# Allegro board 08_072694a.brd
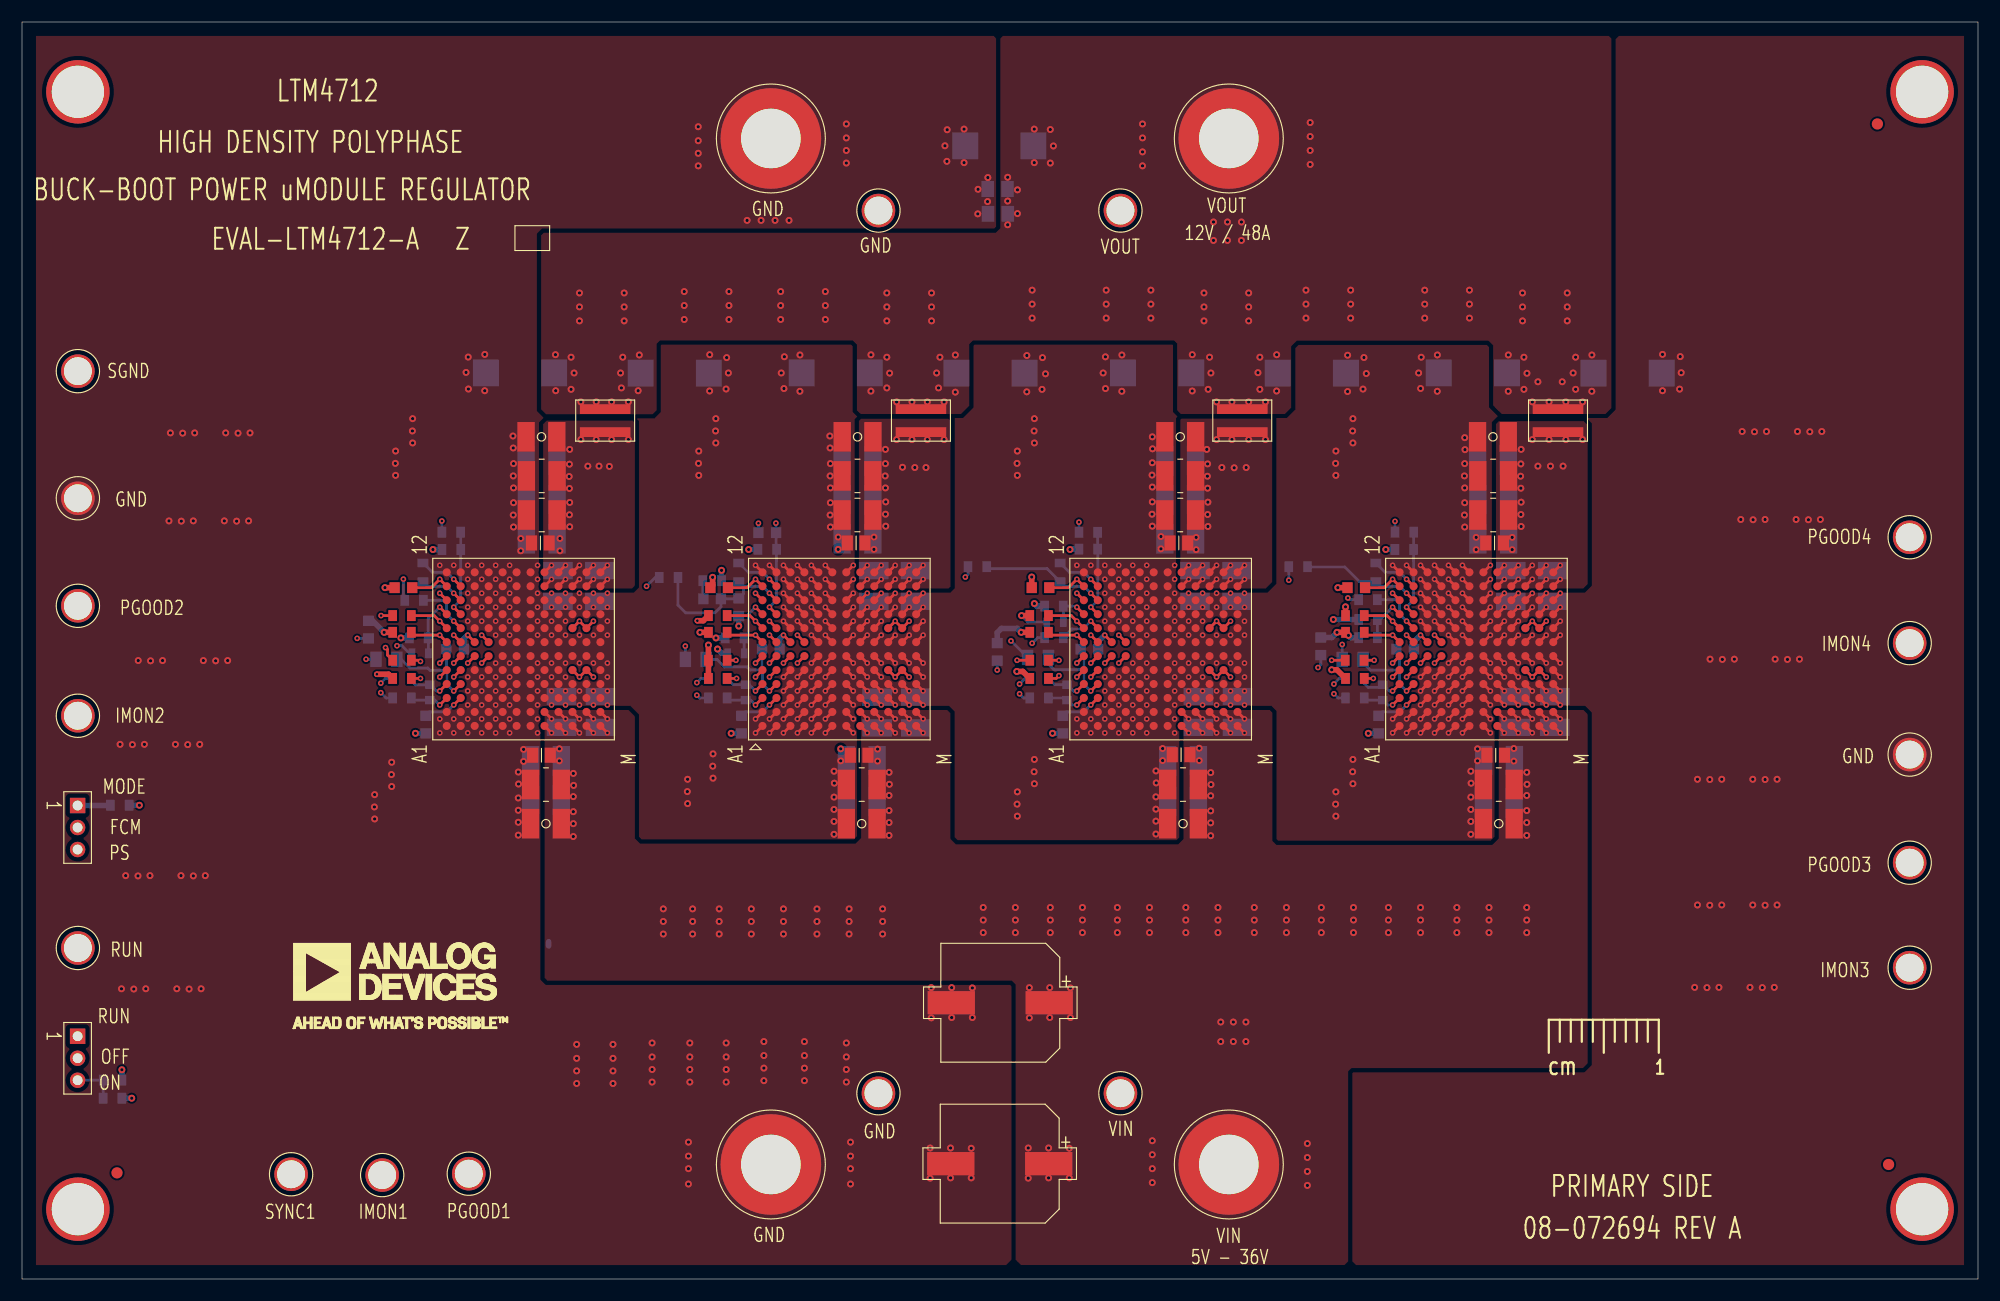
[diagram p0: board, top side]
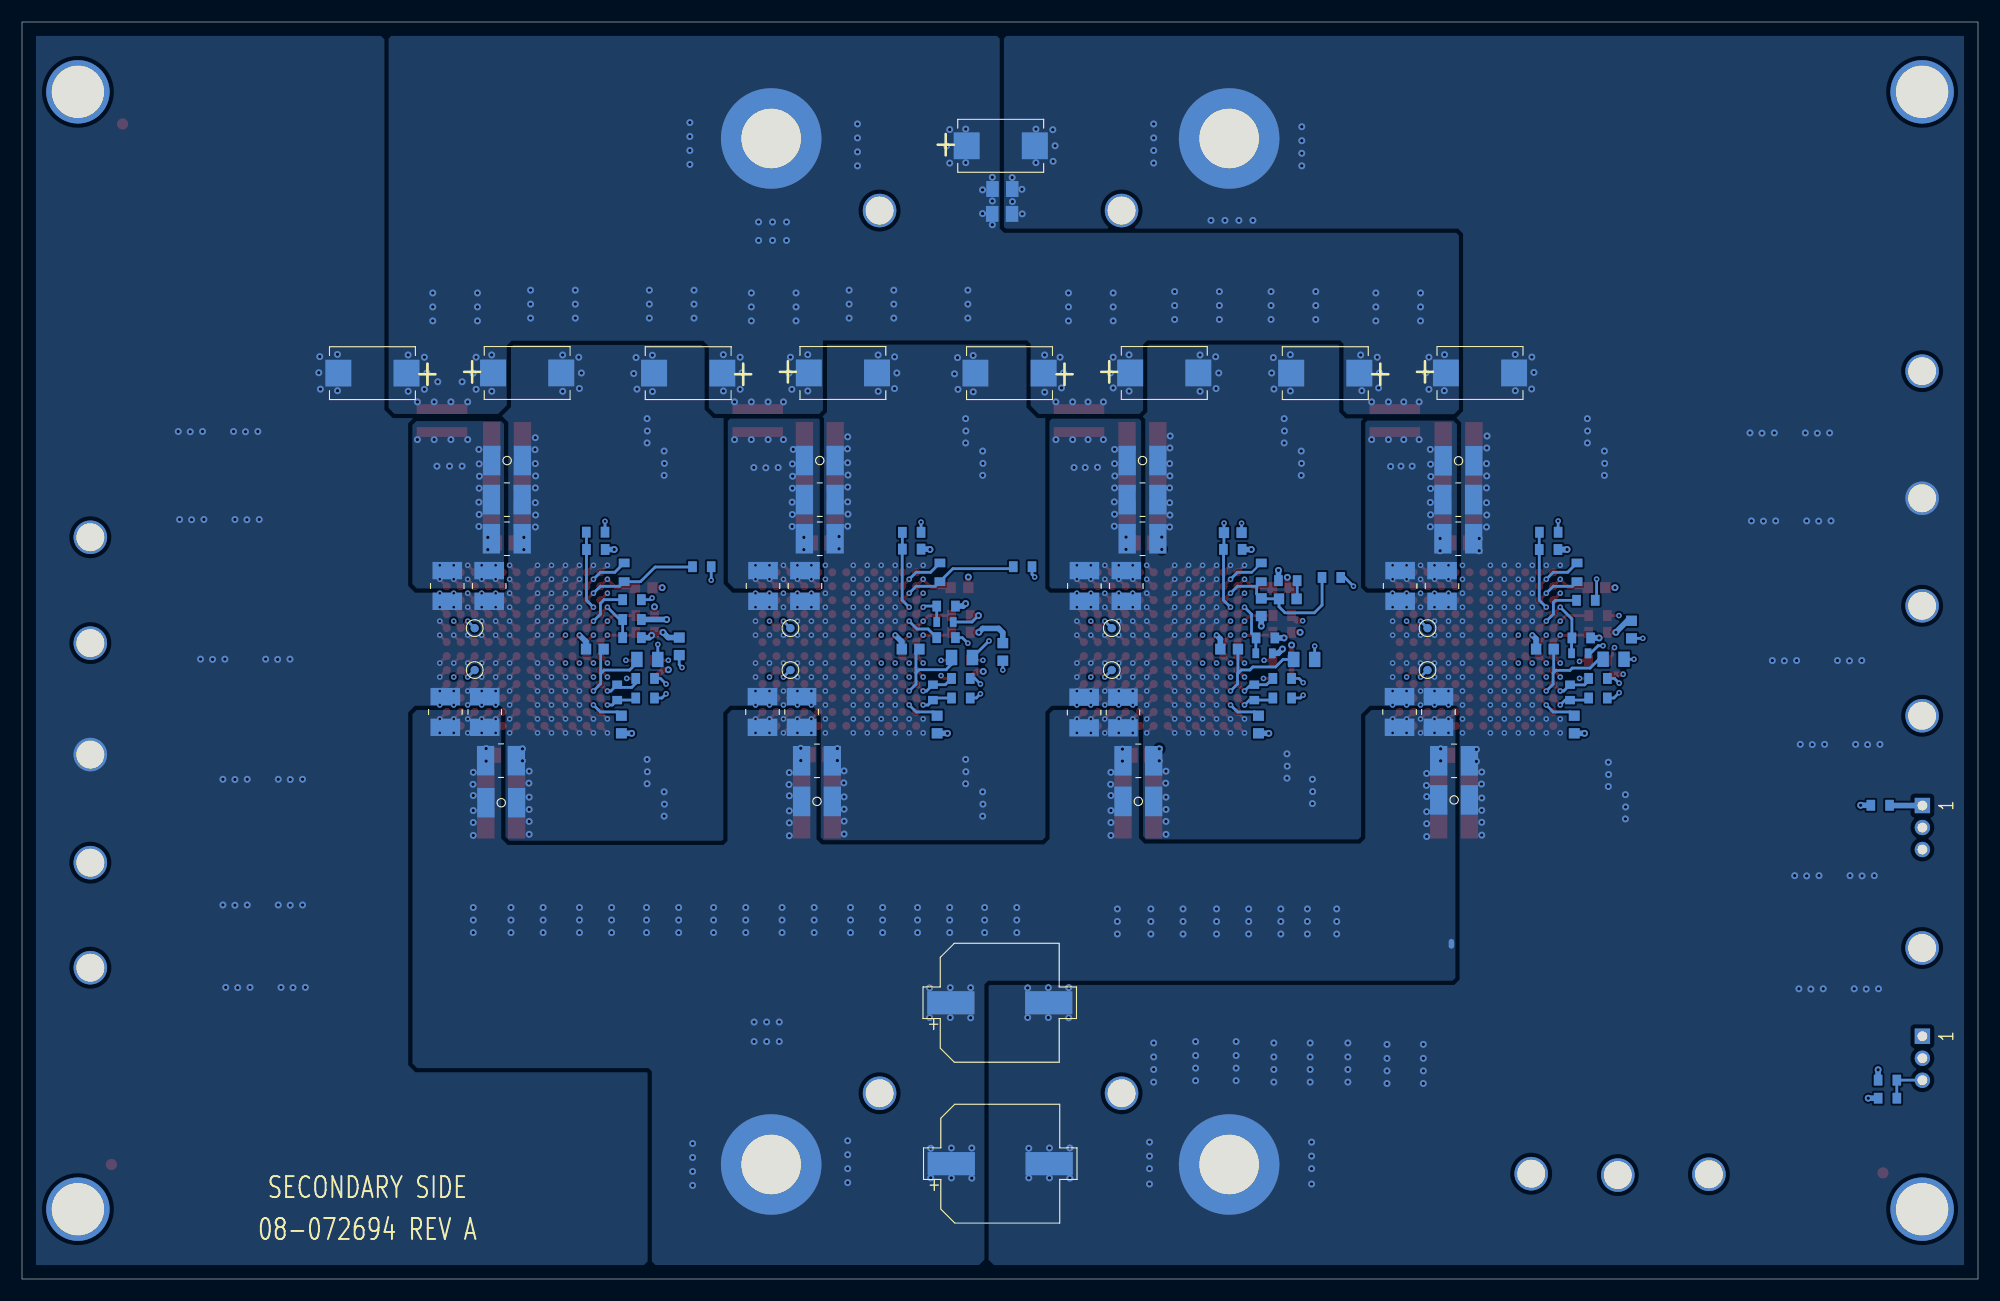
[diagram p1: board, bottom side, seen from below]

Outline 177.8 x 114.3 mm; copper layers: TOP, L2-GND, L3-INT1, L4-INT2, L5-INT3, L6-INT4, L7-GND, BOTTOM. Coordinates in mm from the lower left corner of the outline.
Outline path: 0,114.3 0,0 177.8,0 177.8,114.3 0,114.3

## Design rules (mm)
constraint set DEFAULT: min track width 0.254

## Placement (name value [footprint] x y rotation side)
C1  150UF  [CPLSMSQ406H413]  88.87 10.49 180 bottom
C3  TBD1210  [C1210]  76.33 41.4 0 top
C4  10uF  [C1210-2]  76.33 44.96 0 top
C5  10uF  [C1210-2]  77.72 51.51 270 bottom
C6  0.1uF  [C0603]  63.37 62.86 0 top
C7  10uF  [C1210-2]  81.25 51.51 270 bottom
C8  10uF  [C1210-2]  76.33 47.12 0 bottom
C9  0.1UF  [C0805]  76.1 47.62 0 top
C10  TBD0603  [C0603]  65.15 61.09 90 bottom
C11  TBD0603  [C0603]  62.74 61.85 0 bottom
C12  2.2uF  [C0603]  65.41 50.42 90 bottom
C13  1UF  [C0603#2]  65.79 53.34 90 bottom
C14  TBD0603  [C0603]  67.74 67.87 180 bottom
C15  0.1UF  [C0805]  75.82 66.93 0 top
C16  22uF  [C1210-2]  75.95 69.47 0 top
C17  22uF  [C1210-2]  75.95 73.03 0 top
C18  22uF  [C1210-2]  81.23 63.02 90 bottom
C19  22uF  [C1210-2]  77.42 63.02 90 bottom
C20  22uF  [C1210-2]  75.95 67.31 0 bottom
C21  22uF  [C1210-2]  75.95 70.87 0 bottom
C22  TBD1210  [C1210]  75.95 76.58 0 top
C23  TBD1210  [C1210]  75.95 74.42 0 bottom
C24  100UF  [C7343-20]  73.97 82.39 180 bottom
C25  100UF  [C7343-20]  88.03 82.37 0 bottom
C26  0.1UF  [C0805#2]  88.71 96.85 0 bottom
C27  150UF  [CPLSMSQ406H413]  88.93 25.12 180 bottom
C29  TBD1210  [C1210]  47.63 41.4 0 top
C30  10uF  [C1210-2]  47.63 44.96 0 top
C31  10uF  [C1210-2]  52.58 51.56 270 bottom
C32  0.1uF  [C0603]  34.67 62.86 0 top
C33  10uF  [C1210-2]  49.05 51.56 270 bottom
C34  10uF  [C1210-2]  47.63 47.12 0 bottom
C35  0.1UF  [C0805]  47.22 47.62 0 top
C36  2.2uF  [C0603]  36.7 50.42 90 bottom
C37  1UF  [C0603#2]  37.08 53.34 90 bottom
C38  0.1UF  [C0805]  47.12 66.93 0 top
C39  22uF  [C1210-2]  47.24 70.87 0 bottom
C40  22uF  [C1210-2]  52.53 63.02 90 bottom
C41  22uF  [C1210-2]  48.72 63.02 90 bottom
C42  22uF  [C1210-2]  47.24 67.31 0 bottom
C43  22uF  [C1210-2]  47.24 69.47 0 top
C44  22uF  [C1210-2]  47.24 73.03 0 top
C45  TBD1210  [C1210]  47.22 76.58 0 top
C46  TBD1210  [C1210]  47.22 74.4 0 bottom
C47  100UF  [C7343-20]  45.27 82.39 180 bottom
C48  100UF  [C7343-20]  59.33 82.37 0 bottom
C49  0.1UF  [C0805#2]  88.68 99.11 0 bottom
C50  150UF  [CPLSMSQ406H413]  88.87 10.49 180 top
C52  TBD1210  [C1210]  105.54 41.4 0 top
C53  10uF  [C1210-2]  105.54 44.96 0 top
C54  10uF  [C1210-2]  110.49 51.56 270 bottom
C55  0.1uF  [C0603]  92.58 62.86 0 top
C56  10uF  [C1210-2]  106.93 51.56 270 bottom
C57  10uF  [C1210-2]  105.54 47.12 0 bottom
C58  0.1UF  [C0805]  105.36 47.68 0 top
C59  2.2uF  [C0603]  94.61 50.42 90 bottom
C60  1UF  [C0603#2]  95 53.34 90 bottom
C61  0.1UF  [C0805]  105.16 66.93 0 top
C62  22uF  [C1210-2]  110.44 63.02 90 bottom
C63  22uF  [C1210-2]  106.63 63.02 90 bottom
C64  22uF  [C1210-2]  105.28 69.47 0 top
C65  22uF  [C1210-2]  105.28 70.87 0 bottom
C66  22uF  [C1210-2]  105.28 67.31 0 bottom
C67  22uF  [C1210-2]  105.28 73.03 0 top
C68  TBD1210  [C1210]  105.28 76.58 0 top
C69  TBD1210  [C1210]  105.28 74.42 0 bottom
C70  100UF  [C7343-20]  117.24 82.37 0 bottom
C71  100UF  [C7343-20]  103.18 82.39 180 bottom
C72  100UF  [C7343-20]  88.83 103.04 180 bottom
C73  150UF  [CPLSMSQ406H413]  88.93 25.12 180 top
C75  TBD1210  [C1210]  134.24 41.4 0 top
C76  10uF  [C1210-2]  139.32 51.56 270 bottom
C77  10uF  [C1210-2]  134.24 44.96 0 top
C78  0.1uF  [C0603]  121.28 62.86 0 top
C79  10uF  [C1210-2]  135.74 51.56 270 bottom
C80  10uF  [C1210-2]  134.26 47.13 0 bottom
C81  0.1UF  [C0805]  133.96 47.62 0 top
C82  2.2uF  [C0603]  123.32 50.42 90 bottom
C83  1UF  [C0603#2]  123.7 53.34 90 bottom
C84  0.1UF  [C0805]  133.86 66.93 0 top
C85  22uF  [C1210-2]  139.14 63.02 90 bottom
C86  22uF  [C1210-2]  135.33 63.02 90 bottom
C87  22uF  [C1210-2]  133.73 69.47 0 top
C88  22uF  [C1210-2]  133.73 70.87 0 bottom
C89  22uF  [C1210-2]  133.73 67.31 0 bottom
C90  22uF  [C1210-2]  133.73 73.03 0 top
C91  TBD1210  [C1210]  133.71 76.58 0 top
C92  TBD1210  [C1210]  133.71 74.42 0 bottom
C93  100UF  [C7343-20]  131.88 82.39 180 bottom
C94  100UF  [C7343-20]  145.95 82.37 0 bottom
C95  1uF  [C0603]  68.07 57.28 180 bottom
C96  TBD1210  [C1210]  76.33 43.43 0 bottom
C97  1uF  [C0603]  39.37 57.28 180 bottom
C98  TBD1210  [C1210]  47.63 43.56 0 bottom
C99  TBD0603  [C0603]  31.5 59.06 90 bottom
C100  TBD1210  [C1210]  105.54 43.43 0 bottom
C101  1uF  [C0603]  97.03 57.28 180 bottom
C102  TBD0603  [C0603]  88.65 57.02 90 bottom
C103  TBD1210  [C1210]  134.24 43.31 0 bottom
C104  1uF  [C0603]  125.73 57.28 180 bottom
C105  TBD0603  [C0603]  118.06 57.53 90 bottom
NOREF  -  []  30.89 1.52 0 top
NOREF#2  -  []  -283.54 -217.55 0 top
NOREF#3  -  []  92.07 155.07 0 top
NOREF#4  -  []  -278.76 63.12 0 top
NOREF#5  -  []  -242.38 157.73 0 top
NOREF#6  -  [unnamed#2]  5.08 107.95 0 top
NOREF#7  -  []  177.8 0 90 top
NOREF#8  -  []  -283.54 -217.55 0 top
NOREF#9  -  [unnamed#2]  172.72 107.95 0 top
NOREF#10  -  []  -255.91 283.46 0 top
NOREF#11  -  []  285.12 248.54 0 top
NOREF#12  -  [unnamed#2]  172.72 6.35 0 top
NOREF#13  -  [unnamed#2]  8.64 9.65 0 top
NOREF#14  -  [unnamed#2]  5.08 6.35 0 top
NOREF#15  -  []  138.79 23.57 0 top
NOREF#16  -  [unnamed#2]  169.67 10.41 0 top
NOREF#17  -  []  24.74 20.75 0 top
NOREF#18  -  []  -283.54 -217.55 0 top
NOREF#19  -  [unnamed#2]  168.66 105.03 0 top
NOREF#20  -  []  153.97 14.68 270 top
NOREF#21  -  []  0 114.3 0 top
NOREF#22  -  []  32.51 23.5 0 top
NOREF#23  -  []  -252.2 260.6 0 top
NOREF#24  -  []  12.7 274.57 0 top
NOREF#25  -  []  -252.15 237.74 0 top
NOREF#26  -  []  -129.54 -142.62 0 top
P1  62000311121  [CNTHMHDR1X3L236W79H244]  5.05 22.07 270 top
P2  62000311121  [CNTHMHDR1X3L236W79H244]  5.05 43.05 270 top
R1  100K  [R0603]  63.25 60.33 180 top
R2  0  [R0603]  8.89 43.08 180 bottom
R3  158K  [R0603]  63.25 58.8 0 top
R4  0  [R0603]  64.9 56.9 180 bottom
R5  TBD0603  [R0603]  64.77 58.29 0 bottom
R6  TBD0603  [R0603]  63.25 54.61 0 top
R7  TBD0603  [R0603]  62.74 63.5 180 bottom
R8  1MEG  [R0603]  8.23 16.44 0 bottom
R9  365K  [R0603]  8.23 18.08 180 bottom
R10  0  [R0603]  65.15 64.26 270 bottom
R11  0  [R0805]  61.25 56.34 180 bottom
R12  2.26K  [R0603]  67.74 66.34 0 bottom
R13  100  [R0603]  63.25 54.61 0 bottom
R14  0.002  [R1508]  81.71 78.05 90 top
R15  100  [R0603]  63.25 52.83 0 bottom
R16  100K  [R0603]  34.54 60.33 180 top
R17  0  [R0603]  34.54 56.26 180 top
R18  0  [R0603]  35.64 61.71 180 bottom
R19  158K  [R0603]  34.54 58.8 0 top
R20  0  [R0603]  36.2 56.9 180 bottom
R21  TBD0603  [R0603]  36.07 58.29 0 bottom
R22  TBD0603  [R0603]  34.54 54.61 0 top
R23  0  [R0603]  36.45 64.26 270 bottom
R24  0  [R0805]  33.13 56.35 180 bottom
R25  TBD0603  [R0603]  39.03 66.33 0 bottom
R26  0  [R0603]  39.02 67.91 0 bottom
R27  100  [R0603]  34.54 54.61 0 bottom
R28  0.002  [R1508]  53.01 78.05 90 top
R29  100  [R0603]  34.54 52.83 0 bottom
R30  100K  [R0603]  92.46 60.33 180 top
R31  0  [R0603]  92.46 56.26 180 top
R32  0  [R0603]  93.8 58.32 180 bottom
R33  158K  [R0603]  92.46 58.8 0 top
R34  0  [R0603]  93.9 59.74 180 bottom
R35  TBD0603  [R0603]  93.8 61.19 0 bottom
R36  TBD0603  [R0603]  92.46 54.61 0 top
R37  0  [R0603]  94.36 64.26 270 bottom
R38  0  [R0805]  92.35 56.52 180 bottom
R39  TBD0603  [R0603]  96.93 66.37 0 bottom
R40  0  [R0603]  96.93 67.89 0 bottom
R41  100  [R0603]  92.46 54.61 0 bottom
R42  0.002  [R1508]  110.92 78.05 90 top
R43  100  [R0603]  92.46 52.83 0 bottom
R44  100K  [R0603]  121.16 60.33 180 top
R45  0  [R0603]  121.13 56.26 180 top
R46  0  [R0603]  122.35 61.77 180 bottom
R47  158K  [R0603]  121.16 58.8 0 top
R48  0  [R0603]  122.35 59.97 180 bottom
R49  TBD0603  [R0603]  122.35 58.32 0 bottom
R50  TBD0603  [R0603]  121.16 54.61 0 top
R51  0  [R0603]  123.06 64.26 270 bottom
R52  0  [R0805]  120.95 56.34 180 bottom
R53  TBD0603  [R0603]  125.64 66.33 0 bottom
R54  0  [R0603]  125.66 67.91 0 bottom
R55  100  [R0603]  121.16 54.61 0 bottom
R56  0.002  [R1508]  139.62 78.05 90 top
R57  100  [R0603]  121.16 52.83 0 bottom
R58  0  [R0603]  63.25 56.26 0 top
R59  0  [R0603]  58.78 63.79 0 bottom
R60  0  [R0603]  86.84 64.77 180 bottom
R61  0  [R0603]  116 64.77 180 bottom
SNS1  SNS  [NCSNS25MIL]  70.49 58.55 90 top
SNS2  SNS  [NCSNS25MIL]  41.78 58.54 90 top
SNS3  SNS  [NCSNS25MIL]  99.69 58.55 90 top
SNS4  SNS  [NCSNS25MIL]  128.39 58.55 90 top
TP1  575-4  [CNBANANAD312LD203]  109.7 10.41 0 top
TP2  575-4  [CNBANANAD312LD203]  68.07 10.41 0 top
TP3  2501-2-00-80-00-00-07-0  [CNMILLMAX2501]  99.85 16.89 0 top
TP4  2501-2-00-80-00-00-07-0  [CNMILLMAX2501]  77.85 16.89 0 top
TP5  2501-2-00-80-00-00-07-0  [CNMILLMAX2501]  5.08 30.1 0 top
TP6  2501-2-00-80-00-00-07-0  [CNMILLMAX2501]  40.61 9.58 0 top
TP7  2501-2-00-80-00-00-07-0  [CNMILLMAX2501]  32.74 9.45 0 top
TP8  2501-2-00-80-00-00-07-0  [CNMILLMAX2501]  24.46 9.53 0 top
TP10  2501-2-00-80-00-00-07-0  [CNMILLMAX2501]  5.08 82.55 0 top
TP11  2501-2-00-80-00-00-07-0  [CNMILLMAX2501]  5.08 70.99 0 top
TP14  TESTPAD  [TPSMC30]  78.74 55.37 180 bottom
TP15  TESTPAD  [TPSMC30]  78.74 59.18 180 bottom
TP17  2501-2-00-80-00-00-07-0  [CNMILLMAX2501]  99.85 97.16 0 top
TP18  2501-2-00-80-00-00-07-0  [CNMILLMAX2501]  77.85 97.16 0 top
TP19  575-4  [CNBANANAD312LD203]  109.7 103.71 0 top
TP20  575-4  [CNBANANAD312LD203]  68.07 103.71 0 top
TP21  2501-2-00-80-00-00-07-0  [CNMILLMAX2501]  5.08 61.21 0 top
TP22  2501-2-00-80-00-00-07-0  [CNMILLMAX2501]  5.08 51.22 0 top
TP27  TESTPAD  [TPSMC30]  50.04 55.37 180 bottom
TP28  TESTPAD  [TPSMC30]  50.04 59.18 180 bottom
TP29  2501-2-00-80-00-00-07-0  [CNMILLMAX2501]  171.59 37.86 0 top
TP30  2501-2-00-80-00-00-07-0  [CNMILLMAX2501]  171.59 28.31 0 top
TP35  TESTPAD  [TPSMC30]  107.95 55.37 180 bottom
TP36  TESTPAD  [TPSMC30]  107.95 59.18 180 bottom
TP37  2501-2-00-80-00-00-07-0  [CNMILLMAX2501]  171.59 67.45 0 top
TP38  2501-2-00-80-00-00-07-0  [CNMILLMAX2501]  171.59 57.82 0 top
TP41  2501-2-00-80-00-00-07-0  [CNMILLMAX2501]  171.59 47.69 0 top
TP43  TESTPAD  [TPSMC30]  136.65 55.37 180 bottom
TP44  TESTPAD  [TPSMC30]  136.65 59.18 180 bottom
U1  LTM4712EY#PBF  [BGA144_16X16_8_68]  74.29 57.28 90 top
U2  LTM4712EY#PBF  [BGA144_16X16_8_68]  45.59 57.28 90 top
U3  LTM4712EY#PBF  [BGA144_16X16_8_68]  103.5 57.28 90 top
U4  LTM4712EY#PBF  [BGA144_16X16_8_68]  132.21 57.28 90 top

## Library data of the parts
C1 C27 C50 C73 = CAPP: User Part Number: UPN; Tolerance: 20; alternate symbols: (); part number: CAPP_SM-150UF,50V,20,E042587,CPLSMSQ406H413; tolerance: 20
C3 C22 C23 C29 C45 C46 C52 C68 C69 C75 C91 C92 C96 C98 C100 C103 = CAP: User Part Number: UPN; alternate symbols: (C1210L); part number: CAP_SM-TBD1210,TBD1210,TBD1210,E016202,C1210
C4 C5 C7 C8 C30 C31 C33 C34 C53 C54 C56 C57 C76 C77 C79 C80 = CAP: Tolerance: 10; User Part Number: UPN; alternate symbols: (); part number: CAP_SM-10UF,50V,10,E022361,C1210-2; tolerance: 10
C6 C32 C55 C78 = CAP: User Part Number: UPN; Tolerance: 10; alternate symbols: (C0603L); part number: CAP_SM-0.1UF,16V,10,E015036,C0603; tolerance: 10
C9 C15 C26 C35 C38 C49 C58 C61 C81 C84 = CAP: User Part Number: UPN; Tolerance: 10; alternate symbols: (C0805L); part number: CAP_SM-0.1UF,50V,10,E062481,C0805; tolerance: 10
C10 C11 C14 C99 C102 C105 = CAP: User Part Number: UPN; alternate symbols: (C0603L,C0603L_ALT); part number: CAP_SM-TBD0603,TBD0603,TBD0603,E000382,C0603
C12 C36 C59 C82 = CAP: User Part Number: UPN; Tolerance: 10; alternate symbols: (C0603L); part number: CAP_SM-2.2UF,10V,10,E015288,C0603; tolerance: 10
C13 C37 C60 C83 = CAP: User Part Number: UPN; Tolerance: 10; alternate symbols: (C0603L); part number: CAP_SM-1UF,50V,10,E064098,C0603; tolerance: 10
C16-C21 C39-C44 C62-C67 C85-C90 = CAP: Tolerance: 10; User Part Number: UPN; alternate symbols: (); part number: CAP_SM-22UF,16V,10,E011548,C1210-2; tolerance: 10
C24 C25 C47 C48 C70-C72 C93 C94 = CAPP: Tolerance: 20; User Part Number: UPN; alternate symbols: (); part number: CAPP_SM-100UF,16V,20,E062482,C7343-20; tolerance: 20
C95 C97 C101 C104 = CAP: User Part Number: UPN; Tolerance: 10; alternate symbols: (C0603L); part number: CAP_SM-1UF,16V,10,E025399,C0603; tolerance: 10
P1 P2 = CN3P: User Part Number: UPN; Tolerance: N/A; alternate symbols: (); part number: CN3P_TH-62000311121,E033291,CNTHMHDR1X3L236W79H244; tolerance: N/A
R1 R16 R30 R44 = RES: User Part Number: UPN; Tolerance: 1; alternate symbols: (R0603L); part number: RES_SM-100K,E030871,1/10W,1,R0603; tolerance: 1
R2 R4 R10 R17 R18 R20 R23 R26 R31 R32 R34 R37 R40 R45 R46 R48 R51 R54 R58-R61 = RES: User Part Number: UPN; Tolerance: JUMPER; alternate symbols: (R0603L); part number: RES_SM-0,E007502,1/10W,JUMPER,R0603; tolerance: JUMPER
R3 R19 R33 R47 = RES: User Part Number: UPN; Tolerance: 1; alternate symbols: (R0603L); part number: RES_SM-158K,E045514,1/10W,1,R0603; tolerance: 1
R5-R7 R21 R22 R25 R35 R36 R39 R49 R50 R53 = RES: User Part Number: UPN; alternate symbols: (R0603L); part number: RES_SM-TBD0603,E004050,TBD0603,TBD0603,R0603
R8 = RES: User Part Number: UPN; Tolerance: 1; alternate symbols: (R0603L); part number: RES_SM-1MEG,E030873,1/10W,1,R0603; tolerance: 1
R9 = RES: User Part Number: UPN; Tolerance: 1; alternate symbols: (R0603L); part number: RES_SM-365K,E062399,1/10W,1,R0603; tolerance: 1
R11 R24 R38 R52 = RES: User Part Number: UPN; Tolerance: JUMPER; alternate symbols: (R0805L); part number: RES_SM-0,E030875,1/8W,JUMPER,R0805; tolerance: JUMPER
R12 = RES: User Part Number: UPN; Tolerance: 1.0; alternate symbols: (R0603L); part number: RES_SM-2.26K,E062398,1/10W,1.0,R0603; tolerance: 1.0
R13 R15 R27 R29 R41 R43 R55 R57 = RES: User Part Number: UPN; Tolerance: 1; alternate symbols: (R0603L); part number: RES_SM-100,E003668,1/10W,1,R0603; tolerance: 1
R14 R28 R42 R56 = RES: Tolerance: 1; User Part Number: UPN; alternate symbols: (); part number: RES_SM-0.002,E047758,1W,1,R1508; tolerance: 1
SNS1-SNS4 = NCSENSE: User Part Number: UPN; Tolerance: N/A; alternate symbols: (); part number: NCSENSE_SM-SNS,E002514,NCSNS25MIL; tolerance: N/A
TP1 TP2 TP19 TP20 = CNTP1P: Tolerance: N/A; User Part Number: UPN; alternate symbols: (); part number: CNTP1P_TH-575-4,E012555,CNBANANAD312LD203; tolerance: N/A
TP3-TP8 TP10 TP11 TP17 TP18 TP21 TP22 TP29 TP30 TP37 TP38 TP41 = CNTP1P: User Part Number: UPN; Tolerance: N/A; alternate symbols: (); part number: CNTP1P_TH-2501-2-00-80-00-00-07-0,E031108,CNMILLMAX2501; tolerance: N/A
TP14 TP15 TP27 TP28 TP35 TP36 TP43 TP44 = NCTESTPAD: Tolerance: N/A; User Part Number: UPN; alternate symbols: (); part number: NCTESTPAD_SM-TESTPAD,E012884,TPSMC30; tolerance: N/A
U1-U4 = ADLTM4712: Tolerance: N/A; alternate symbols: (); part number: ADLTM4712_SM-LTM4712EY#PBF,E059323,BGA144_16X16_8_68; tolerance: N/A

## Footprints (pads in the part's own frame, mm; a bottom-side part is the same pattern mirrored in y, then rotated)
BGA144_16X16_8_68
  round 0.73 smd: A1(-6.985,6.985) A2(-5.715,6.985) A3(-4.445,6.985) A4(-3.175,6.985) A5(-1.905,6.985) A6(-0.635,6.985) A7(0.635,6.985) A8(1.905,6.985) A9(3.175,6.985) A10(4.445,6.985) A11(5.715,6.985) A12(6.985,6.985) B1(-6.985,5.715) B2(-5.715,5.715) B3(-4.445,5.715) B4(-3.175,5.715) B5(-1.905,5.715) B6(-0.635,5.715) B7(0.635,5.715) B8(1.905,5.715) B9(3.175,5.715) B10(4.445,5.715) B11(5.715,5.715) B12(6.985,5.715) C1(-6.985,4.445) C2(-5.715,4.445) C3(-4.445,4.445) C4(-3.175,4.445) C5(-1.905,4.445) C6(-0.635,4.445) C7(0.635,4.445) C8(1.905,4.445) C9(3.175,4.445) C10(4.445,4.445) C11(5.715,4.445) C12(6.985,4.445) D1(-6.985,3.175) D2(-5.715,3.175) D3(-4.445,3.175) D4(-3.175,3.175) D5(-1.905,3.175) D6(-0.635,3.175) D7(0.635,3.175) D8(1.905,3.175) D9(3.175,3.175) D10(4.445,3.175) D11(5.715,3.175) D12(6.985,3.175) E1(-6.985,1.905) E2(-5.715,1.905) E3(-4.445,1.905) E4(-3.175,1.905) E5(-1.905,1.905) E6(-0.635,1.905) E7(0.635,1.905) E8(1.905,1.905) E9(3.175,1.905) E10(4.445,1.905) E11(5.715,1.905) E12(6.985,1.905) F1(-6.985,0.635) F2(-5.715,0.635) F3(-4.445,0.635) F4(-3.175,0.635) F5(-1.905,0.635) F6(-0.635,0.635) F7(0.635,0.635) F8(1.905,0.635) F9(3.175,0.635) F10(4.445,0.635) F11(5.715,0.635) F12(6.985,0.635) G1(-6.985,-0.635) G2(-5.715,-0.635) G3(-4.445,-0.635) G4(-3.175,-0.635) G5(-1.905,-0.635) G6(-0.635,-0.635) G7(0.635,-0.635) G8(1.905,-0.635) G9(3.175,-0.635) G10(4.445,-0.635) G11(5.715,-0.635) G12(6.985,-0.635) H1(-6.985,-1.905) H2(-5.715,-1.905) H3(-4.445,-1.905) H4(-3.175,-1.905) H5(-1.905,-1.905) H6(-0.635,-1.905) H7(0.635,-1.905) H8(1.905,-1.905) H9(3.175,-1.905) H10(4.445,-1.905) H11(5.715,-1.905) H12(6.985,-1.905) J1(-6.985,-3.175) J2(-5.715,-3.175) J3(-4.445,-3.175) J4(-3.175,-3.175) J5(-1.905,-3.175) J6(-0.635,-3.175) J7(0.635,-3.175) J8(1.905,-3.175) J9(3.175,-3.175) J10(4.445,-3.175) J11(5.715,-3.175) J12(6.985,-3.175) K1(-6.985,-4.445) K2(-5.715,-4.445) K3(-4.445,-4.445) K4(-3.175,-4.445) K5(-1.905,-4.445) K6(-0.635,-4.445) K7(0.635,-4.445) K8(1.905,-4.445) K9(3.175,-4.445) K10(4.445,-4.445) K11(5.715,-4.445) K12(6.985,-4.445) L1(-6.985,-5.715) L2(-5.715,-5.715) L3(-4.445,-5.715) L4(-3.175,-5.715) L5(-1.905,-5.715) L6(-0.635,-5.715) L7(0.635,-5.715) L8(1.905,-5.715) L9(3.175,-5.715) L10(4.445,-5.715) L11(5.715,-5.715) L12(6.985,-5.715) M1(-6.985,-6.985) M2(-5.715,-6.985) M3(-4.445,-6.985) M4(-3.175,-6.985) M5(-1.905,-6.985) M6(-0.635,-6.985) M7(0.635,-6.985) M8(1.905,-6.985) M9(3.175,-6.985) M10(4.445,-6.985) M11(5.715,-6.985) M12(6.985,-6.985)
C0603
  rect 0.94x0.991 smd: 1(-0.8,0) 2(0.8,0)
C0603#2
  rect 0.762x0.889 smd: 1(-0.7,0) 2(0.7,0)
C0805
  rect 1.016x1.372 smd: 1(-0.803,0) 2(0.803,0)
C0805#2
  rect 1.143x1.448 smd: 1(-0.9,0) 2(0.9,0)
C1210
  rect 1.575x2.692 smd: 1(-1.397,0) 2(1.397,0)
C1210-2
  rect 1.575x2.692 smd: 1(-1.397,0) 2(1.397,0)
C7343-20
  rect 2.362x2.438 smd: N(3.1,0) P(-3.1,0)
CNBANANAD312LD203
  round 9.144 hole 5.41: 1(0,0)
CNMILLMAX2501
  round 3.048 hole 2.54: 1(0,0)
CNTHMHDR1X3L236W79H244
  rect 1.397x1.397 hole 0.889: 1(0,0)
  round 1.397 hole 0.889: 2(2,0) 3(4,0)
CPLSMSQ406H413
  rect 4.293x2.108 smd: N(4.45,0) P(-4.45,0)
NCSNS25MIL
  round 0.127 smd: 1(0,0) 2(1.27,0)
R0603
  rect 0.787x0.991 smd: 1(-0.85,0) 2(0.85,0)
R0805
  rect 1.041x1.397 smd: 1(-0.95,0) 2(0.95,0)
R1508
  rect 0.889x4.597 smd: 1(-1.044,0) 2(1.044,0)
TPSMC30
  round 0.762 smd: 1(0,0)
unnamed#2
  round 5.766 hole 4.75 unplated: (0,0)

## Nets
GND_POWER: C1.N(N2) C3.1 C4.1 C5.1 C7.1 C8.1 C9.1 C15.1 C16.1 C17.1 C18.1 C19.1 C20.1 C21.1 C22.1 C23.1 C24.N(N2) C25.N(N2) C26.1 C27.N(N2) C29.1 C30.1 C31.1 C33.1 C34.1 C35.1 C38.1 C39.1 C40.1 C41.1 C42.1 C43.1 C44.1 C45.1 C46.1 C47.N(N2) C48.N(N2) C49.1 C50.N(N2) C52.1 C53.1 C54.1 C56.1 C57.1 C58.1 C61.1 C62.1 C63.1 C64.1 C65.1 C66.1 C67.1 C68.1 C69.1 C70.N(N2) C71.N(N2) C72.N(N2) C73.N(N2) C75.1 C76.1 C77.1 C79.1 C80.1 C81.1 C84.1 C85.1 C86.1 C87.1 C88.1 C89.1 C90.1 C91.1 C92.1 C93.N(N2) C94.N(N2) C96.1 C98.1 C100.1 C103.1 SNS1.2(N2) SNS2.2(N2) SNS3.2(N2) SNS4.2(N2) TP2.1(N1) TP4.1(N1) TP11.1(N1) TP18.1(N1) TP20.1(N1) TP41.1(N1) U1.A1 U1.A2 U1.A12 U1.B1 U1.B2 U1.B12 U1.C1 U1.C2 U1.C3 U1.C4 U1.C5 U1.C8 U1.C9 U1.C10 U1.C11 U1.C12 U1.D1 U1.D2 U1.D3 U1.D4 U1.D5 U1.D8 U1.D9 U1.D10 U1.D11 U1.D12 U1.E1 U1.E2 U1.E3 U1.E4 U1.E5 U1.E6 U1.E7 U1.E8 U1.E9 U1.E10 U1.E11 U1.E12 U1.F1 U1.F2 U1.F3 U1.F4 U1.F5 U1.F6 U1.F7 U1.F8 U1.F9 U1.F10 U1.F11 U1.F12 U1.G1 U1.G2 U1.G3 U1.G4 U1.G5 U1.G6 U1.G7 U1.G8 U1.G9 U1.G10 U1.G11 U1.G12 U1.H3 U1.H4 U1.H5 U1.H6 U1.H7 U1.H8 U1.H9 U1.H10 U1.J3 U1.J4 U1.J5 U1.J6 U1.J7 U1.J8 U1.J9 U1.J10 U1.K3 U1.K4 U1.K6 U1.K7 U1.K9 U1.K10 U1.L3 U1.L4 U1.L6 U1.L7 U1.L9 U1.L10 U1.M3 U1.M4 U1.M5 U1.M6 U1.M7 U1.M8 U1.M9 U1.M10 U2.A1 U2.A2 U2.A12 U2.B1 U2.B2 U2.B12 U2.C1 U2.C2 U2.C3 U2.C4 U2.C5 U2.C8 U2.C9 U2.C10 U2.C11 U2.C12 U2.D1 U2.D2 U2.D3 U2.D4 U2.D5 U2.D8 U2.D9 U2.D10 U2.D11 U2.D12 U2.E1 U2.E2 U2.E3 U2.E4 U2.E5 U2.E6 U2.E7 U2.E8 U2.E9 U2.E10 U2.E11 U2.E12 U2.F1 U2.F2 U2.F3 U2.F4 U2.F5 U2.F6 U2.F7 U2.F8 U2.F9 U2.F10 U2.F11 U2.F12 U2.G1 U2.G2 U2.G3 U2.G4 U2.G5 U2.G6 U2.G7 U2.G8 U2.G9 U2.G10 U2.G11 U2.G12 U2.H3 U2.H4 U2.H5 U2.H6 U2.H7 U2.H8 U2.H9 U2.H10 U2.J3 U2.J4 U2.J5 U2.J6 U2.J7 U2.J8 U2.J9 U2.J10 U2.K3 U2.K4 U2.K6 U2.K7 U2.K9 U2.K10 U2.L3 U2.L4 U2.L6 U2.L7 U2.L9 U2.L10 U2.M3 U2.M4 U2.M5 U2.M6 U2.M7 U2.M8 U2.M9 U2.M10 U3.A1 U3.A2 U3.A12 U3.B1 U3.B2 U3.B12 U3.C1 U3.C2 U3.C3 U3.C4 U3.C5 U3.C8 U3.C9 U3.C10 U3.C11 U3.C12 U3.D1 U3.D2 U3.D3 U3.D4 U3.D5 U3.D8 U3.D9 U3.D10 U3.D11 U3.D12 U3.E1 U3.E2 U3.E3 U3.E4 U3.E5 U3.E6 U3.E7 U3.E8 U3.E9 U3.E10 U3.E11 U3.E12 U3.F1 U3.F2 U3.F3 U3.F4 U3.F5 U3.F6 U3.F7 U3.F8 U3.F9 U3.F10 U3.F11 U3.F12 U3.G1 U3.G2 U3.G3 U3.G4 U3.G5 U3.G6 U3.G7 U3.G8 U3.G9 U3.G10 U3.G11 U3.G12 U3.H3 U3.H4 U3.H5 U3.H6 U3.H7 U3.H8 U3.H9 U3.H10 U3.J3 U3.J4 U3.J5 U3.J6 U3.J7 U3.J8 U3.J9 U3.J10 U3.K3 U3.K4 U3.K6 U3.K7 U3.K9 U3.K10 U3.L3 U3.L4 U3.L6 U3.L7 U3.L9 U3.L10 U3.M3 U3.M4 U3.M5 U3.M6 U3.M7 U3.M8 U3.M9 U3.M10 U4.A1 U4.A2 U4.A12 U4.B1 U4.B2 U4.B12 U4.C1 U4.C2 U4.C3 U4.C4 U4.C5 U4.C8 U4.C9 U4.C10 U4.C11 U4.C12 U4.D1 U4.D2 U4.D3 U4.D4 U4.D5 U4.D8 U4.D9 U4.D10 U4.D11 U4.D12 U4.E1 U4.E2 U4.E3 U4.E4 U4.E5 U4.E6 U4.E7 U4.E8 U4.E9 U4.E10 U4.E11 U4.E12 U4.F1 U4.F2 U4.F3 U4.F4 U4.F5 U4.F6 U4.F7 U4.F8 U4.F9 U4.F10 U4.F11 U4.F12 U4.G1 U4.G2 U4.G3 U4.G4 U4.G5 U4.G6 U4.G7 U4.G8 U4.G9 U4.G10 U4.G11 U4.G12 U4.H3 U4.H4 U4.H5 U4.H6 U4.H7 U4.H8 U4.H9 U4.H10 U4.J3 U4.J4 U4.J5 U4.J6 U4.J7 U4.J8 U4.J9 U4.J10 U4.K3 U4.K4 U4.K6 U4.K7 U4.K9 U4.K10 U4.L3 U4.L4 U4.L6 U4.L7 U4.L9 U4.L10 U4.M3 U4.M4 U4.M5 U4.M6 U4.M7 U4.M8 U4.M9 U4.M10
GND_SIGNAL: C6.1 C10.1 C12.1 C32.1 C36.1 C55.1 C59.1 C78.1 C82.1 C95.1 C97.1 C99.2(N2) C101.1 C102.2(N2) C104.1 C105.2(N2) P1.1 R2.1 R3.1 R5.1 R6.1 R7.1 R9.1 R12.1 R19.1 R21.1 R22.1 R25.1 R33.1 R35.1 R36.1 R39.1 R47.1 R49.1 R50.1 R53.1 R58.1 SNS1.1 SNS2.1 SNS3.1 SNS4.1 TP10.1(N1) U1.B7 U1.C6 U1.C7 U1.D6 U1.D7 U2.B7 U2.C6 U2.C7 U2.D6 U2.D7 U3.B7 U3.C6 U3.C7 U3.D6 U3.D7 U4.B7 U4.C6 U4.C7 U4.D6 U4.D7
VIN: C1.P C3.2(N2) C4.2(N2) C5.2(N2) C7.2(N2) C8.2(N2) C9.2(N2) C27.P C29.2(N2) C30.2(N2) C31.2(N2) C33.2(N2) C34.2(N2) C35.2(N2) C50.P C52.2(N2) C53.2(N2) C54.2(N2) C56.2(N2) C57.2(N2) C58.2(N2) C73.P C75.2(N2) C76.2(N2) C77.2(N2) C79.2(N2) C80.2(N2) C81.2(N2) C96.2(N2) C98.2(N2) C100.2(N2) C103.2(N2) R8.2(N2) TP1.1(N1) TP3.1(N1) U1.H1 U1.H2 U1.J1 U1.J2 U1.K1 U1.K2 U1.L1 U1.L2 U1.M1 U1.M2 U2.H1 U2.H2 U2.J1 U2.J2 U2.K1 U2.K2 U2.L1 U2.L2 U2.M1 U2.M2 U3.H1 U3.H2 U3.J1 U3.J2 U3.K1 U3.K2 U3.L1 U3.L2 U3.M1 U3.M2 U4.H1 U4.H2 U4.J1 U4.J2 U4.K1 U4.K2 U4.L1 U4.L2 U4.M1 U4.M2
CLKOUT1: R17.2(N2) U1.A6
CLKOUT2: R31.2(N2) U2.A6
CLKOUT3: R45.2(N2) U3.A6
COMP: C10.2(N2) C11.2(N2) R10.2(N2) R59.2(N2) R60.2(N2) R61.2(N2) U1.B10
FB: C14.1 R12.2(N2) R26.1 R40.1 R54.1 U1.B9
IMON1: TP7.1(N1) U1.A5
IMON2: TP22.1(N1) U2.A5
IMON3: TP30.1(N1) U3.A5
IMON4: TP38.1(N1) U4.A5
INTVCC1: C12.2(N2) R1.2(N2) R4.2(N2) U1.B3
INTVCC2: C36.2(N2) R16.2(N2) R20.2(N2) U2.B3
INTVCC3: C59.2(N2) R30.2(N2) R34.2(N2) R48.2(N2) U3.B3
INTVCC4: C82.2(N2) R44.2(N2) U4.B3
ISN1: C13.1 R15.2(N2) U1.A3
ISN2: C37.1 R29.2(N2) U2.A3
ISN3: C60.1 R43.2(N2) U3.A3
ISN4: C83.1 R57.2(N2) U4.A3
ISP1: C13.2(N2) R13.2(N2) U1.A4
ISP2: C37.2(N2) R27.2(N2) U2.A4
ISP3: C60.2(N2) R41.2(N2) U3.A4
ISP4: C83.2(N2) R55.2(N2) U4.A4
MODE: P2.2 U1.A10 U2.A10 U3.A10 U4.A10
PGOOD1: R1.1 TP6.1(N1) U1.A8
PGOOD2: R16.1 TP21.1(N1) U2.A8
PGOOD3: R30.1 TP29.1(N1) U3.A8
PGOOD4: R44.1 TP37.1(N1) U4.A8
RUN: P1.2 R18.2(N2) R32.2(N2) R46.2(N2) TP5.1(N1) U1.B8
SOFTSTART: C6.2(N2) C32.2(N2) C55.2(N2) C78.2(N2) U1.A11 U2.A11 U3.A11 U4.A11
SYNC1: R58.2(N2) TP8.1(N1) U1.B6
UNNAMED_1_ADLTM4712_I1_COMPB: R10.1 U1.B11
UNNAMED_1_ADLTM4712_I1_EXTVCC: C95.2(N2) R11.1 U1.B4
UNNAMED_1_ADLTM4712_I1_FREQ: R3.2(N2) U1.A7
UNNAMED_1_ADLTM4712_I1_ISET: R6.2(N2) U1.B5
UNNAMED_1_ADLTM4712_I1_PHMODE: R4.1 R5.2(N2) U1.A9
UNNAMED_1_ADLTM4712_I1_SW1: TP14.1(N1) U1.K5 U1.L5
UNNAMED_1_ADLTM4712_I1_SW2: TP15.1(N1) U1.K8 U1.L8
UNNAMED_1_ADLTM4712_I1_VOUT: C14.2(N2) C15.2(N2) C16.2(N2) C17.2(N2) C18.2(N2) C19.2(N2) C20.2(N2) C21.2(N2) C22.2(N2) C23.2(N2) R11.2(N2) R13.1 R14.1 TP17.1(N1) U1.H11 U1.H12 U1.J11 U1.J12 U1.K11 U1.K12 U1.L11 U1.L12 U1.M11(VOUT_9) U1.M12
UNNAMED_1_CAP_I39_N1: C11.1 R7.2(N2)
UNNAMED_1_CN3P_I129_N3: P1.3(N3) R8.1 R9.2(N2)
UNNAMED_1_CN3P_I130_N1: P2.1 R2.2(N2)
UNNAMED_2_ADLTM4712_I17_COMPA: R23.2(N2) R59.1 U2.B10
UNNAMED_2_ADLTM4712_I17_COMPB: R23.1 U2.B11
UNNAMED_2_ADLTM4712_I17_EXTVCC: C97.2(N2) R24.1 U2.B4
UNNAMED_2_ADLTM4712_I17_FB: R25.2(N2) R26.2(N2) U2.B9
UNNAMED_2_ADLTM4712_I17_FREQ: R19.2(N2) U2.A7
UNNAMED_2_ADLTM4712_I17_ISET: R22.2(N2) U2.B5
UNNAMED_2_ADLTM4712_I17_PHMODE: R20.1 R21.2(N2) U2.A9
UNNAMED_2_ADLTM4712_I17_RUN: R18.1 U2.B8
UNNAMED_2_ADLTM4712_I17_SW1: TP27.1(N1) U2.K5 U2.L5
UNNAMED_2_ADLTM4712_I17_SW2: TP28.1(N1) U2.K8 U2.L8
UNNAMED_2_ADLTM4712_I17_SYNC: C99.1 R17.1 U2.B6
UNNAMED_2_ADLTM4712_I17_VOUT: C38.2(N2) C39.2(N2) C40.2(N2) C41.2(N2) C42.2(N2) C43.2(N2) C44.2(N2) C45.2(N2) C46.2(N2) R24.2(N2) R27.1 R28.1 U2.H11 U2.H12 U2.J11 U2.J12 U2.K11 U2.K12 U2.L11 U2.L12 U2.M11(VOUT_9) U2.M12
UNNAMED_3_ADLTM4712_I10_COMPA: R37.2(N2) R60.1 U3.B10
UNNAMED_3_ADLTM4712_I10_COMPB: R37.1 U3.B11
UNNAMED_3_ADLTM4712_I10_EXTVCC: C101.2(N2) R38.1 U3.B4
UNNAMED_3_ADLTM4712_I10_FB: R39.2(N2) R40.2(N2) U3.B9
UNNAMED_3_ADLTM4712_I10_FREQ: R33.2(N2) U3.A7
UNNAMED_3_ADLTM4712_I10_ISET: R36.2(N2) U3.B5
UNNAMED_3_ADLTM4712_I10_PHMODE: R34.1 R35.2(N2) U3.A9
UNNAMED_3_ADLTM4712_I10_RUN: R32.1 U3.B8
UNNAMED_3_ADLTM4712_I10_SW1: TP35.1(N1) U3.K5 U3.L5
UNNAMED_3_ADLTM4712_I10_SW2: TP36.1(N1) U3.K8 U3.L8
UNNAMED_3_ADLTM4712_I10_SYNC: C102.1 R31.1 U3.B6
UNNAMED_3_ADLTM4712_I10_VOUT: C61.2(N2) C62.2(N2) C63.2(N2) C64.2(N2) C65.2(N2) C66.2(N2) C67.2(N2) C68.2(N2) C69.2(N2) R38.2(N2) R41.1 R42.1 U3.H11 U3.H12 U3.J11 U3.J12 U3.K11 U3.K12 U3.L11 U3.L12 U3.M11(VOUT_9) U3.M12
UNNAMED_4_ADLTM4712_I11_COMPA: R51.2(N2) R61.1 U4.B10
UNNAMED_4_ADLTM4712_I11_COMPB: R51.1 U4.B11
UNNAMED_4_ADLTM4712_I11_EXTVCC: C104.2(N2) R52.1 U4.B4
UNNAMED_4_ADLTM4712_I11_FB: R53.2(N2) R54.2(N2) U4.B9
UNNAMED_4_ADLTM4712_I11_FREQ: R47.2(N2) U4.A7
UNNAMED_4_ADLTM4712_I11_ISET: R50.2(N2) U4.B5
UNNAMED_4_ADLTM4712_I11_PHMODE: R48.1 R49.2(N2) U4.A9
UNNAMED_4_ADLTM4712_I11_RUN: R46.1 U4.B8
UNNAMED_4_ADLTM4712_I11_SW1: TP43.1(N1) U4.K5 U4.L5
UNNAMED_4_ADLTM4712_I11_SW2: TP44.1(N1) U4.K8 U4.L8
UNNAMED_4_ADLTM4712_I11_SYNC: C105.1 R45.1 U4.B6
UNNAMED_4_ADLTM4712_I11_VOUT: C84.2(N2) C85.2(N2) C86.2(N2) C87.2(N2) C88.2(N2) C89.2(N2) C90.2(N2) C91.2(N2) C92.2(N2) R52.2(N2) R55.1 R56.1 U4.H11 U4.H12 U4.J11 U4.J12 U4.K11 U4.K12 U4.L11 U4.L12 U4.M11(VOUT_9) U4.M12
VOUT: C24.P C25.P C26.2(N2) C47.P C48.P C49.2(N2) C70.P C71.P C72.P C93.P C94.P R14.2(N2) R15.1 R28.2(N2) R29.1 R42.2(N2) R43.1 R56.2(N2) R57.1 TP19.1(N1)

Pads without a net: P2 3; U4 A6

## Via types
v1: diameter 0.508, hole 0.254, TOP to BOTTOM, 617 vias
v2: diameter 0.635, hole 0.305, TOP to BOTTOM, 673 vias

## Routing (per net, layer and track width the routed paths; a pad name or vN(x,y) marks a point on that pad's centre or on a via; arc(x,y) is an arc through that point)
GND_POWER: length 272.2
  TOP w0.254: U1.K9 v1(79.38,61.09) ; U4.C11 v1(127.13,63.63) ; U4.K4 v1(137.29,53.47) ; U4.D4 v1(128.4,53.47) ; U4.C10 v1(127.13,62.36) ; U4.J4 v1(136.02,53.47) ; U4.L6 v1(138.56,56.01) ; U1.D4 v1(70.49,53.47) ; U1.C10 v1(69.22,62.36) ; U4.G1 v1(133.48,49.66) ; U4.C4 v1(127.13,53.47) ; U4.M5 v1(139.83,54.74) ; U1.C3 v1(69.22,52.2) ; U1.F2 v1(73.03,50.93) ; U4.E9 v1(129.67,61.09) ; U4.F4 v1(130.94,53.47) ; U1.E5 v1(71.75,54.74) ; U1.E12 v1(71.75,64.9) ; U4.L10 v1(138.56,62.36) ; U4.G4 v1(133.48,53.47) ; U1.J10 v1(78.1,62.36) ; U4.J3 v1(136.02,52.2) ; U4.M8 v1(139.83,59.82) ; U1.G5 v1(75.56,54.74) ; U1.B1 v1(67.94,49.66) ; U1.K6 v1(79.38,56.01) ; U1.J4 v1(78.1,53.47) ; U4.D1 v1(128.4,49.66) ; U1.L7 v1(80.64,58.55) ; U4.M6 v1(139.83,56.01) ; U1.A2 v1(66.68,50.93) ; U1.K10 v1(79.38,62.36) ; U4.G9 v1(133.48,61.09) ; U4.E6 v1(129.67,56.01) ; U4.E1 v1(129.67,49.66) ; U1.G4 v1(75.56,53.47) ; U4.C1 v1(127.13,49.66) ; U4.C3 v1(127.13,52.2) ; U1.B12 v1(67.94,64.9) ; U1.F12 v1(73.03,64.9) ; U1.D8 v1(70.49,59.82) ; U1.M5 v1(81.91,54.74) ; U4.J5 v1(136.02,54.74) ; U4.E10 v1(129.67,62.36) ; U4.D10 v1(128.4,62.36) ; U1.M4 v1(81.91,53.47) ; U4.C5 v1(127.13,54.74) ; U4.F10 v1(130.94,62.36) ; U1.L3 v1(80.64,52.2) ; U4.F3 v1(130.94,52.2) ; U4.J6 v1(136.02,56.01) ; U1.G7 v1(75.56,58.55) ; U4.L7 v1(138.56,58.55) ; U1.K3 v1(79.38,52.2) ; U4.F12 v1(130.94,64.9) ; U1.F4 v1(73.03,53.47) ; U1.C9 v1(69.22,61.09) ; U1.F5 v1(73.03,54.74) ; U4.C9 v1(127.13,61.09) ; U4.K7 v1(137.29,58.55) ; U1.G6 v1(75.56,56.01) ; U4.H3 v1(134.75,52.2) ; U1.L10 v1(80.64,62.36) ; U4.C12 v1(127.13,64.9) ; U4.H8 v1(134.75,59.82) ; U4.K9 v1(137.29,61.09) ; U4.F6 v1(130.94,56.01) ; U4.G6 v1(133.48,56.01) ; U1.M8 v1(81.91,59.82) ; U4.G7 v1(133.48,58.55) ; U1.M9 v1(81.91,61.09) ; U4.M7 v1(139.83,58.55) ; U1.D10 v1(70.49,62.36) ; U1.B2 v1(67.94,50.93) ; U1.D2 v1(70.49,50.93) ; U1.G12 v1(75.56,64.9) ; U4.E12 v1(129.67,64.9) ; U4.E11 v1(129.67,63.63) ; U1.E11 v1(71.75,63.63) ; U4.G8 v1(133.48,59.82) ; U4.G11 v1(133.48,63.63) ; U1.J5 v1(78.1,54.74) ; U1.H8 v1(76.84,59.82) ; U1.C11 v1(69.22,63.63) ; U4.L3 v1(138.56,52.2) ; U4.D8 v1(128.4,59.82) ; U1.D1 v1(70.49,49.66) ; U4.K10 v1(137.29,62.36) ; U1.E1 v1(71.75,49.66) ; U4.F5 v1(130.94,54.74) ; U4.F7 v1(130.94,58.55) ; U1.D11 v1(70.49,63.63) ; U1.G2 v1(75.56,50.93) ; U1.J3 v1(78.1,52.2) ; U4.A12 v1(124.59,64.9) ; U1.G11 v1(75.56,63.63) ; U4.E8 v1(129.67,59.82) ; U1.D5 v1(70.49,54.74) ; U4.H10 v1(134.75,62.36) ; U4.K6 v1(137.29,56.01) ; U4.F1 v1(130.94,49.66) ; U4.H4 v1(134.75,53.47) ; U4.J7 v1(136.02,58.55) ; U4.F8 v1(130.94,59.82) ; U1.G10 v1(75.56,62.36) ; U4.D2 v1(128.4,50.93) ; U1.C2 v1(69.22,50.93) ; U1.J8 v1(78.1,59.82) ; U4.M10 v1(139.83,62.36) ; U4.E2 v1(129.67,50.93) ; U1.E10 v1(71.75,62.36) ; U1.K4 v1(79.38,53.47) ; U4.F9 v1(130.94,61.09) ; U1.G9 v1(75.56,61.09) ; U4.D12 v1(128.4,64.9) ; U4.A1 v1(124.59,49.66) ; U1.M6 v1(81.91,56.01) ; U1.M10 v1(81.91,62.36) ; U1.C1 v1(69.22,49.66) ; U1.J6 v1(78.1,56.01) ; U4.D9 v1(128.4,61.09) ; U4.H5 v1(134.75,54.74) ; U1.F6 v1(73.03,56.01) ; U4.C2 v1(127.13,50.93) ; U1.H6 v1(76.84,56.01) ; U1.D3 v1(70.49,52.2) ; U1.G8 v1(75.56,59.82) ; U1.M7 v1(81.91,58.55) ; U1.D9 v1(70.49,61.09) ; U4.B1 v1(125.86,49.66) ; U1.M3 v1(81.91,52.2) ; U1.H7 v1(76.84,58.55) ; U1.D12 v1(70.49,64.9) ; U4.M9 v1(139.83,61.09) ; U1.L9 v1(80.64,61.09) ; U4.L9 v1(138.56,61.09) ; U1.E6 v1(71.75,56.01) ; U1.H5 v1(76.84,54.74) ; U1.C4 v1(69.22,53.47) ; U4.D5 v1(128.4,54.74) ; U1.F3 v1(73.03,52.2) ; U1.F11 v1(73.03,63.63) ; U4.E4 v1(129.67,53.47) ; U1.F7 v1(73.03,58.55) ; U4.B12 v1(125.86,64.9) ; U4.G12 v1(133.48,64.9) ; U1.H10 v1(76.84,62.36) ; U1.E2 v1(71.75,50.93) ; U1.G3 v1(75.56,52.2) ; U1.F9 v1(73.03,61.09) ; U1.F8 v1(73.03,59.82) ; U4.E7 v1(129.67,58.55) ; U4.H6 v1(134.75,56.01) ; U1.E7 v1(71.75,58.55) ; U4.F11 v1(130.94,63.63) ; U4.K3 v1(137.29,52.2) ; U4.E3 v1(129.67,52.2) ; U4.B2 v1(125.86,50.93) ; U1.F1 v1(73.03,49.66) ; U1.E8 v1(71.75,59.82) ; U4.G10 v1(133.48,62.36) ; U4.J9 v1(136.02,61.09) ; U4.M4 v1(139.83,53.47) ; U1.J7 v1(78.1,58.55) ; U1.C5 v1(69.22,54.74) ; U1.E4 v1(71.75,53.47) ; U1.E3 v1(71.75,52.2) ; U1.C12 v1(69.22,64.9) ; U1.H4 v1(76.84,53.47) ; U1.K7 v1(79.38,58.55) ; U1.L6 v1(80.64,56.01) ; U4.G3 v1(133.48,52.2) ; U1.L4 v1(80.64,53.47) ; U1.H3 v1(76.84,52.2) ; U4.M3 v1(139.83,52.2) ; U1.F10 v1(73.03,62.36) ; U4.A2 v1(124.59,50.93) ; U1.C8 v1(69.22,59.82) ; U4.L4 v1(138.56,53.47) ; U4.G5 v1(133.48,54.74) ; U4.F2 v1(130.94,50.93) ; U1.A1 v1(66.68,49.66) ; U4.D3 v1(128.4,52.2) ; U1.J9 v1(78.1,61.09) ; U4.D11 v1(128.4,63.63) ; U4.J10 v1(136.02,62.36) ; U4.G2 v1(133.48,50.93) ; U4.E5 v1(129.67,54.74) ; U4.H9 v1(134.75,61.09) ; U1.H9 v1(76.84,61.09) ; U4.H7 v1(134.75,58.55) ; U1.A12 v1(66.68,64.9) ; U4.J8 v1(136.02,59.82) ; U4.C8 v1(127.13,59.82) ; U1.E9 v1(71.75,61.09) ; U1.G1 v1(75.56,49.66)
  L3-INT1 w0.254: TP4.1 84.94,16.89 88.37,20.32 88.37,27.91 75.62,40.66 75.62,47.75 75.16,48.21 v2(74.42,48.21) ; TP18.1 77.86,97.16 83.19,97.16 88.37,91.99 88.37,81.45 85.02,78.1 76.63,78.1 75.34,76.81 75.34,66.85 74.83,66.34 v2(74.19,66.34)
  L6-INT4 w0.254: 77.57,55.85 77.09,55.37
  vias: v1(37.97,64.9) v1(37.97,50.93) v1(37.97,49.66) v1(39.24,64.9) v1(39.24,50.93) v1(39.24,49.66) v1(40.51,64.9) v1(40.51,63.63) v1(40.51,62.36) v1(40.51,61.09) v1(40.51,59.82) v1(40.51,54.74) v1(40.51,53.47) v1(40.51,52.2) v1(40.51,50.93) v1(40.51,49.66) v1(41.78,64.9) v1(41.78,63.63) v1(41.78,62.36) v1(41.78,61.09) v1(41.78,59.82) v1(41.78,54.74) v1(41.78,53.47) v1(41.78,52.2) v1(41.78,50.93) v1(41.78,49.66) v1(43.05,64.9) v1(43.05,63.63) v1(43.05,62.36) v1(43.05,61.09) v1(43.05,59.82) v1(43.05,58.55) v1(43.05,56.01) v1(43.05,54.74) v1(43.05,53.47) v1(43.05,52.2) v1(43.05,50.93) v1(43.05,49.66) v1(44.32,64.9) v1(44.32,63.63) v1(44.32,62.36) v1(44.32,61.09) v1(44.32,59.82) v1(44.32,58.55) v1(44.32,56.01) v1(44.32,54.74) v1(44.32,53.47) v1(44.32,52.2) v1(44.32,50.93) v1(44.32,49.66) v1(46.86,64.9) v1(46.86,63.63) v1(46.86,62.36) v1(46.86,61.09) v1(46.86,59.82) v1(46.86,58.55) v1(46.86,56.01) v1(46.86,54.74) v1(46.86,53.47) v1(46.86,52.2) v1(46.86,50.93) v1(46.86,49.66) v1(48.13,62.36) v1(48.13,61.09) v1(48.13,59.82) v1(48.13,58.55) v1(48.13,56.01) v1(48.13,54.74) v1(48.13,53.47) v1(48.13,52.2) v1(49.4,62.36) v1(49.4,61.09) v1(49.4,59.82) v1(49.4,58.55) v1(49.4,56.01) v1(49.4,54.74) v1(49.4,53.47) v1(49.4,52.2) v1(50.67,62.36) v1(50.67,61.09) v1(50.67,58.55) v1(50.67,56.01) v1(50.67,53.47) v1(50.67,52.2) v1(51.94,62.36) v1(51.94,61.09) v1(51.94,58.55) v1(51.94,56.01) v1(51.94,53.47) v1(51.94,52.2) v1(53.21,62.36) v1(53.21,61.09) v1(53.21,59.82) v1(53.21,58.55) v1(53.21,56.01) v1(53.21,54.74) v1(53.21,53.47) v1(53.21,52.2) v1(95.88,64.9) v1(95.88,50.93) v1(95.88,49.66) v1(97.16,64.9) v1(97.16,50.93) v1(97.16,49.66) v1(98.42,64.9) v1(98.42,63.63) v1(98.42,62.36) v1(98.42,61.09) v1(98.42,59.82) v1(98.42,54.74) v1(98.42,53.47) v1(98.42,52.2) v1(98.42,50.93) v1(98.42,49.66) v1(99.69,64.9) v1(99.69,63.63) v1(99.69,62.36) v1(99.69,61.09) v1(99.69,59.82) v1(99.69,54.74) v1(99.69,53.47) v1(99.69,52.2) v1(99.69,50.93) v1(99.69,49.66) v1(100.97,64.9) v1(100.97,63.63) v1(100.97,62.36) v1(100.97,61.09) v1(100.97,59.82) v1(100.97,58.55) v1(100.97,56.01) v1(100.97,54.74) v1(100.97,53.47) v1(100.97,52.2) v1(100.97,50.93) v1(100.97,49.66) v1(102.23,64.9) v1(102.23,63.63) v1(102.23,62.36) v1(102.23,61.09) v1(102.23,59.82) v1(102.23,58.55) v1(102.23,56.01) v1(102.23,54.74) v1(102.23,53.47) v1(102.23,52.2) v1(102.23,50.93) v1(102.23,49.66) v1(104.78,64.9) v1(104.78,63.63) v1(104.78,62.36) v1(104.78,61.09) v1(104.78,59.82) v1(104.78,58.55) v1(104.78,56.01) v1(104.78,54.74) v1(104.78,53.47) v1(104.78,52.2) v1(104.78,50.93) v1(104.78,49.66) v1(106.04,62.36) v1(106.04,61.09) v1(106.04,59.82) v1(106.04,58.55) v1(106.04,56.01) v1(106.04,54.74) v1(106.04,53.47) v1(106.04,52.2) v1(107.31,62.36) v1(107.31,61.09) v1(107.31,59.82) v1(107.31,58.55) v1(107.31,56.01) v1(107.31,54.74) v1(107.31,53.47) v1(107.31,52.2) v1(108.59,62.36) v1(108.59,61.09) v1(108.59,58.55) v1(108.59,56.01) v1(108.59,53.47) v1(108.59,52.2) v1(109.85,62.36) v1(109.85,61.09) v1(109.85,58.55) v1(109.85,56.01) v1(109.85,53.47) v1(109.85,52.2) v1(111.12,62.36) v1(111.12,61.09) v1(111.12,59.82) v1(111.12,58.55) v1(111.12,56.01) v1(111.12,54.74) v1(111.12,53.47) v1(111.12,52.2) v2(8.92,48.62) v2(9.04,26.39) v2(9.42,36.68) v2(10.04,48.59) v2(10.16,26.37) v2(10.57,56.24) v2(10.54,36.65) v2(11.13,48.62) v2(11.25,26.39) v2(11.69,56.21) v2(11.63,36.68) v2(12.78,56.24) v2(13.36,68.94) v2(13.49,76.94) v2(13.94,48.62) v2(14.07,26.39) v2(14.48,68.91) v2(14.45,36.68) v2(14.61,76.91) v2(15.06,48.59) v2(15.19,26.37) v2(15.57,68.94) v2(15.57,36.65) v2(15.7,76.94) v2(16.15,48.62) v2(16.28,26.39) v2(16.48,56.24) v2(16.66,36.68) v2(17.6,56.21) v2(18.39,68.94) v2(18.52,76.94) v2(18.69,56.24) v2(19.51,68.91) v2(19.64,76.91) v2(20.6,68.94) v2(20.73,76.94) v2(32.05,44.04) v2(32.03,42.92) v2(32.05,41.83) v2(33.58,45.87) v2(33.6,46.99) v2(33.6,44.78) v2(33.96,75.29) v2(33.94,74.17) v2(33.96,73.08) v2(35.49,77.11) v2(35.51,78.23) v2(35.51,76.02) v2(40.36,82.44) v2(40.56,83.83) v2(40.58,80.93) v2(42.07,84.07) v2(42.06,80.77) v2(44.63,76.66) v2(44.65,75.56) v2(44.68,74.14) v2(44.66,73.03) v2(44.68,71.93) v2(44.68,70.59) v2(44.66,69.47) v2(44.68,68.38) v2(45.11,46.1) v2(45.14,45.01) v2(45.11,43.74) v2(45.11,42.62) v2(45.11,41.53) v2(45.11,40.36) v2(45.34,67.34) v2(45.34,66.22) v2(45.59,48.16) v2(45.59,47.07) v2(50.42,21.34) v2(50.42,20.07) v2(50.42,18.92) v2(50.42,17.78) v2(53.72,21.34) v2(53.72,20.07) v2(53.72,18.92) v2(53.72,17.78) v2(57.28,21.46) v2(57.28,20.19) v2(57.28,19.05) v2(57.28,17.91) v2(60.48,44.32) v2(60.5,45.44) v2(60.5,43.23) v2(60.58,12.45) v2(60.58,11.18) v2(60.58,10.03) v2(60.58,8.64) v2(60.71,21.46) v2(60.71,20.19) v2(60.71,19.05) v2(60.71,17.91) v2(61.47,104.78) v2(61.47,103.5) v2(61.47,102.36) v2(61.47,101.22) v2(61.5,74.17) v2(61.52,75.29) v2(61.52,73.08) v2(62.51,84.05) v2(62.51,80.75) v2(62.79,46.63) v2(62.81,47.75) v2(62.81,45.54) v2(63.07,78.23) v2(63.04,77.11) v2(63.07,76.02) v2(64,80.93) v2(64.05,83.78) v2(64.01,21.46) v2(64.01,20.19) v2(64.01,19.05) v2(64.01,17.91) v2(64.21,82.38) v2(65.91,96.26) v2(67.18,96.26) v2(67.44,21.59) v2(67.44,20.32) v2(67.44,19.18) v2(67.44,18.03) v2(68.45,96.26) v2(69.02,82.39) v2(69.3,83.86) v2(69.26,80.97) v2(69.72,96.26) v2(70.72,84.02) v2(70.71,80.72) v2(71.12,21.59) v2(71.12,20.32) v2(71.12,19.18) v2(71.12,18.03) v2(73.43,76.66) v2(73.46,75.56) v2(73.48,74.14) v2(73.46,73.03) v2(73.48,71.93) v2(73.48,70.59) v2(73.46,69.47) v2(73.48,68.38) v2(73.81,46.18) v2(73.84,45.08) v2(73.81,43.82) v2(73.81,42.7) v2(73.81,41.61) v2(73.81,40.44) v2(74.19,67.46) v2(74.42,47.12) v2(74.93,105.03) v2(74.93,103.76) v2(74.93,102.62) v2(74.93,101.47) v2(74.93,21.46) v2(74.93,20.19) v2(74.93,19.05) v2(74.93,17.91) v2(75.31,12.45) v2(75.31,11.18) v2(75.31,10.03) v2(75.31,8.64) v2(82.55,11.91) v2(82.55,9.17) v2(82.65,26.49) v2(82.65,23.75) v2(83.89,103.04) v2(84.1,104.5) v2(84.07,101.63) v2(84.4,11.91) v2(84.4,9.19) v2(84.51,26.49) v2(84.51,23.77) v2(85.63,104.56) v2(85.63,101.51) v2(86.28,11.89) v2(86.28,9.19) v2(86.39,26.47) v2(86.39,23.77) v2(86.88,96.85) v2(86.91,99.09) v2(87.8,100.15) v2(87.77,97.97) v2(90.47,75.29) v2(90.45,74.17) v2(90.47,73.08) v2(90.47,44.3) v2(90.45,43.18) v2(90.47,42.09) v2(91.34,83.97) v2(91.33,80.67) v2(92.02,78.23) v2(92,77.11) v2(92.02,76.02) v2(92.02,47.24) v2(92,46.12) v2(92.02,45.03) v2(92.76,83.78) v2(92.72,80.9) v2(93.04,82.31) v2(98.28,82.39) v2(98.48,83.85) v2(98.49,80.97) v2(99.98,84.02) v2(99.97,80.72) v2(102.75,76.58) v2(102.77,75.49) v2(102.74,74.22) v2(102.72,73.1) v2(102.74,72.01) v2(102.74,70.66) v2(102.72,69.55) v2(102.74,68.46) v2(103.08,46.2) v2(103.1,45.11) v2(103.07,43.84) v2(103.07,42.72) v2(103.07,41.63) v2(103.07,40.46) v2(103.53,67.51) v2(103.53,66.4) v2(103.68,48.23) v2(103.68,47.14) v2(119.43,75.29) v2(119.41,74.17) v2(119.43,73.08) v2(119.43,44.3) v2(119.41,43.18) v2(119.43,42.09) v2(120.5,84) v2(120.49,80.7) v2(120.98,78.23) v2(120.96,77.11) v2(120.98,76.02) v2(120.98,47.24) v2(120.96,46.12) v2(120.98,45.03) v2(121.9,80.92) v2(121.98,83.79) v2(122.2,82.33) v2(126.95,82.39) v2(127.19,83.82) v2(127.13,80.98) v2(128.65,84.02) v2(128.65,80.72) v2(131.14,76.5) v2(131.17,75.41) v2(131.14,74.14) v2(131.12,73.03) v2(131.14,71.93) v2(131.14,70.59) v2(131.12,69.47) v2(131.14,68.38) v2(131.7,43.82) v2(131.7,42.7) v2(131.7,41.61) v2(131.7,40.44) v2(131.7,46.18) v2(131.72,45.08) v2(132.18,67.44) v2(132.18,66.32) v2(132.31,48.21) v2(132.31,47.12) v2(149.13,84.08) v2(149.12,80.77) v2(150.68,80.92) v2(150.73,83.87) v2(150.82,82.41) v2(152.04,26.52) v2(152.3,45.44) v2(152.3,34.01) v2(153.16,26.49) v2(153.44,56.36) v2(153.42,45.42) v2(153.42,33.99) v2(154.25,26.52) v2(154.56,56.34) v2(154.51,45.44) v2(154.51,34.01) v2(155.65,56.36) v2(156.24,69.06) v2(156.36,77.06) v2(157.07,26.52) v2(157.36,69.04) v2(157.33,45.44) v2(157.33,34.01) v2(157.48,77.04) v2(158.19,26.49) v2(158.45,69.06) v2(158.45,45.42) v2(158.45,33.99) v2(158.57,77.06) v2(159.28,26.52) v2(159.36,56.36) v2(159.54,45.44) v2(159.54,34.01) v2(160.48,56.34) v2(161.26,69.06) v2(161.39,77.06) v2(161.57,56.36) v2(162.38,69.04) v2(162.51,77.04) v2(163.47,69.06) v2(163.6,77.06)
GND_SIGNAL: length 169.7
  TOP w0.254: U4.D6 v1(128.4,56.01) ; U1.D7 v1(70.49,58.55) ; U2.C6 v1(40.51,56.01) ; U3.C6 v1(98.42,56.01) ; U1.C7 v1(69.22,58.55) ; U2.C7 v1(40.51,58.55) ; U4.C7 v1(127.13,58.55) ; U4.B7 v1(125.86,58.55) ; U4.C6 v1(127.13,56.01) ; U2.D6 v1(41.78,56.01) ; U2.D7 v1(41.78,58.55) ; U1.D6 v1(70.49,56.01) ; U1.B7 v1(67.94,58.55) ; U2.B7 v1(39.24,58.55) ; U3.D6 v1(99.69,56.01) ; U3.B7 v1(97.16,58.55) ; U3.D7 v1(99.69,58.55) ; U4.D7 v1(128.4,58.55) ; U1.C6 v1(69.22,56.01) ; U3.C7 v1(98.42,58.55)
  TOP w0.508: R33.1 v2(90.83,58.8) ; R36.1 90.97,55.25 v2(90.42,55.25) ; R47.1 v2(119.53,58.8) ; R22.1 33.31,54.99 v1(32.26,54.99) ; v2(119.05,55.4) 119.52,55.4 R50.1 ; R6.1 R58.1 v2(62.4,57.65) ; C55.1 v2(91.78,63.83) ; C78.1 v2(119.61,62.86) ; R19.1 v2(32.92,58.8) ; R3.1 v2(61.62,58.8) ; C32.1 v2(32.99,62.86) ; v2(62.78,63.8) 62.78,63.07 C6.1
  L3-INT1 w0.508: 32.92,67.59 17.96,82.55 TP10.1
  L4-INT2 w0.508: v2(10.67,43.08) 20.24,43.08 32.16,54.99 v1(32.26,54.99) ; v2(35.76,49.62) 35.76,42.88 11.91,19.02 v2(9.08,19.02) 6.03,22.07 P1.1
  BOTTOM w0.508: v2(66.05,66.33) 66.88,66.33 R12.1 ; C12.1 v2(64.47,49.62) ; v2(90.83,58.8) 90.47,59.16 89.03,59.16 88.65,58.78 C102.2 ; R7.1 v2(63.59,64.44) ; R49.1 120.78,58.32 v2(120.57,58.52) ; C82.1 v2(122.38,49.62) ; v1(127.13,58.55) 126.53,57.95 C104.1 ; 38.18,66.33 v2(37.35,66.33) 37.35,66.33 R25.1 ; C101.1 97.83,57.95 v1(98.42,58.55) ; R9.1 v2(9.08,19.02) ; C97.1 40.17,58.2 v1(40.51,58.55) ; R39.1 95.3,66.37 v2(95.26,66.33) ; R53.1 v2(123.97,66.33) ; R5.1 v2(63.08,58.29) ; R21.1 v2(34.44,58.29) ; v2(119.53,58.8) 119.06,58.33 C105.2 ; R2.1 v2(10.67,43.08) ; R35.1 92.25,61.19 v2(92.02,61.42) ; C59.1 v2(93.68,49.62) ; C99.2 31.86,59.86 v2(32.92,58.8) ; C95.1 68.87,58.2 v1(69.22,58.55) ; C36.1 v2(35.76,49.62) ; C10.1 v2(65.15,59.37)
VIN: length 138.5
  TOP w0.254: U1.K1 v1(79.38,49.66) ; U3.M1 v1(111.12,49.66) ; U2.J2 v1(49.4,50.93) ; U2.K1 v1(50.67,49.66) ; U4.L2 v1(138.56,50.93) ; U4.K2 v1(137.29,50.93) ; U2.L2 v1(51.94,50.93) ; U4.L1 v1(138.56,49.66) ; U4.J2 v1(136.02,50.93) ; U2.M1 v1(53.21,49.66) ; U1.L1 v1(80.64,49.66) ; U1.M2 v1(81.91,50.93) ; U1.M1 v1(81.91,49.66) ; U4.H1 v1(134.75,49.66) ; U1.K2 v1(79.38,50.93) ; U2.H1 v1(48.13,49.66) ; U4.M2 v1(139.83,50.93) ; U1.H1 v1(76.84,49.66) ; U4.J1 v1(136.02,49.66) ; U3.J2 v1(107.31,50.93) ; U2.H2 v1(48.13,50.93) ; U4.M1 v1(139.83,49.66) ; U4.H2 v1(134.75,50.93) ; U3.L1 v1(109.85,49.66) ; U3.H1 v1(106.04,49.66) ; U1.L2 v1(80.64,50.93) ; U2.M2 v1(53.21,50.93) ; U3.L2 v1(109.85,50.93) ; U2.K2 v1(50.67,50.93) ; U3.M2 v1(111.12,50.93) ; U2.J1 v1(49.4,49.66) ; U3.J1 v1(107.31,49.66) ; U3.H2 v1(106.04,50.93) ; U4.K1 v1(137.29,49.66) ; U3.K2 v1(108.59,50.93) ; U1.J1 v1(78.1,49.66) ; U1.H2 v1(76.84,50.93) ; U1.J2 v1(78.1,50.93) ; U2.L1 v1(51.94,49.66) ; U3.K1 v1(108.59,49.66)
  L3-INT1 w0.254: TP3.1 92.54,16.89 88.9,20.53 88.9,28.14 76.12,40.92 76.12,47.8 76.5,48.18 v2(77.77,48.18)
  L4-INT2 w0.508: v2(58.29,31.37) 30.99,31.37 16.06,16.44 v2(9.98,16.44)
  BOTTOM w0.508: R8.2 v2(9.98,16.44) ; 47.87,30.67 47.87,30.29
  vias: v2(48.84,48.21) v2(48.84,47.12) v2(50.12,45.97) v2(50.14,44.88) v2(50.11,43.87) v2(50.11,42.49) v2(50.11,41.4) v2(50.11,40.23) v2(58.29,33.66) v2(58.29,32.51) v2(60.96,33.66) v2(60.96,32.51) v2(60.96,31.37) v2(63.37,33.66) v2(63.37,32.51) v2(63.37,31.37) v2(66.29,33.66) v2(66.29,32.51) v2(66.29,31.37) v2(69.22,33.66) v2(69.22,32.51) v2(69.22,31.37) v2(72.26,33.66) v2(72.26,32.51) v2(72.26,31.37) v2(75.18,33.66) v2(75.18,32.51) v2(75.18,31.37) v2(77.77,47.09) v2(78.23,33.66) v2(78.23,32.51) v2(78.23,31.37) v2(78.82,46.07) v2(78.84,44.98) v2(78.82,43.97) v2(78.82,42.6) v2(78.82,41.51) v2(78.82,40.34) v2(87.38,33.78) v2(87.38,32.64) v2(87.38,31.5) v2(90.3,33.78) v2(90.3,32.64) v2(90.3,31.5) v2(91.47,11.91) v2(91.47,9.17) v2(91.57,26.49) v2(91.57,23.75) v2(93.32,11.91) v2(93.32,9.19) v2(93.47,33.78) v2(93.47,32.64) v2(93.47,31.5) v2(93.42,26.49) v2(93.42,23.77) v2(95.2,11.89) v2(95.2,9.19) v2(95.3,26.47) v2(95.3,23.77) v2(96.39,33.78) v2(96.39,32.64) v2(96.39,31.5) v2(99.57,33.78) v2(99.57,32.64) v2(99.57,31.5) v2(102.49,33.78) v2(102.49,32.64) v2(102.49,31.5) v2(102.74,12.57) v2(102.74,11.3) v2(102.74,10.03) v2(102.74,8.76) v2(105.79,33.78) v2(105.79,32.64) v2(105.79,31.5) v2(107.01,48.26) v2(107.01,47.14) v2(108.05,46.05) v2(108.08,44.96) v2(108.05,43.94) v2(108.05,42.57) v2(108.05,41.48) v2(108.05,40.31) v2(108.71,33.78) v2(108.71,32.64) v2(108.71,31.5) v2(108.97,23.37) v2(108.97,21.59) v2(110.11,23.37) v2(110.11,21.59) v2(111.25,23.37) v2(111.25,21.59) v2(112.01,33.78) v2(112.01,32.64) v2(112.01,31.5) v2(114.94,33.78) v2(114.94,32.64) v2(114.94,31.5) v2(116.84,12.32) v2(116.84,11.05) v2(116.84,9.78) v2(116.84,8.51) v2(118.11,33.78) v2(118.11,32.64) v2(118.11,31.5) v2(121.03,33.78) v2(121.03,32.64) v2(121.03,31.5) v2(124.21,33.78) v2(124.21,32.64) v2(124.21,31.5) v2(127.13,33.78) v2(127.13,32.64) v2(127.13,31.5) v2(130.43,33.78) v2(130.43,32.64) v2(130.43,31.5) v2(133.35,33.78) v2(133.35,32.64) v2(133.35,31.5) v2(135.61,48.23) v2(135.61,47.09) v2(136.78,46.07) v2(136.78,43.97) v2(136.78,42.6) v2(136.78,41.51) v2(136.78,40.34) v2(136.78,33.78) v2(136.78,32.64) v2(136.78,31.5) v2(136.8,44.98)
CLKOUT1: length 37
  TOP w0.254: v1(33.04,57.42) 33.22,57.24 33.22,56.73 R17.2 ; U1.A6 v1(66.68,56.01)
  L4-INT2 w0.254: v1(33.04,57.42) 35.04,55.42 66.09,55.42 v1(66.68,56.01)
CLKOUT2: length 58.2
  TOP w0.254: R31.2 v1(90.45,56.26) ; U2.A6 v1(37.97,56.01)
  L4-INT2 w0.254: v1(90.45,56.26) 86.21,60.5 59.64,60.5 56.41,57.28 39.24,57.28 v1(37.97,56.01)
CLKOUT3: length 25.8
  TOP w0.254: R45.2 v1(119.05,56.26) ; U3.A6 v1(95.88,56.01)
  L5-INT3 w0.254: v1(119.05,56.26) 118.54,56.77 96.65,56.77 v1(95.88,56.01)
COMP: length 65.5
  TOP w0.254: U1.B10 v1(67.94,62.36)
  L5-INT3 w0.254: v1(67.94,62.36) 68.58,62.99 85.75,62.99 ; v1(115.15,63.54) 114.6,62.99 85.75,62.99 ; 85.75,62.99 v1(85.75,63.83)
  BOTTOM w0.254: 65.57,62.99 67.31,62.99 v1(67.94,62.36) ; 65.57,62.99 65.57,62.31 C10.2 65.11,61.85 C11.2 63.54,61.13 62.99,60.58 60.32,60.58 59.63,61.28 R59.2 ; 65.57,62.99 R10.2 ; v1(85.75,63.83) 85.99,64.07 R60.2 ; R61.2 v1(115.15,63.54)
FB: length 106.8
  TOP w0.254: U1.B9 v1(67.94,61.09)
  L4-INT2 w0.381: 68.53,67.2 68.53,67.2 70.2,65.53 92.79,65.53 v1(96.08,68.82) 99.29,65.61 121.52,65.61 v1(124.81,68.89) ; 68.53,67.2 66.83,65.51 41.58,65.51 v1(38.17,68.93) ; 68.53,67.2 v1(68.53,68.73)
  BOTTOM w0.254: R54.1 v1(124.81,68.89) ; v1(68.53,68.73) 68.54,68.72 C14.1 68.54,66.39 R12.2 68.58,66.33 68.58,61.72 v1(67.94,61.09) ; R26.1 v1(38.17,68.93) ; R40.1 v1(96.08,68.82)
IMON1: length 60.2
  TOP w0.254: U1.A5 v1(66.68,54.74)
  L5-INT3 w0.254: v1(66.68,54.74) 66.68,54.45 65.99,53.76 65.99,47.19 32.74,13.94 TP7.1
IMON2: length 35.2
  TOP w0.254: U2.A5 v1(37.97,54.74)
  L5-INT3 w0.254: TP22.1 34.45,51.22 v1(37.97,54.74)
IMON3: length 94
  TOP w0.254: U3.A5 v1(95.88,54.74)
  L4-INT2 w0.254: v1(95.88,54.74) 94.69,53.54 94.69,46.61 103.05,38.25 161.64,38.25 TP30.1
IMON4: length 49.7
  TOP w0.254: U4.A5 v1(124.59,54.74)
  L4-INT2 w0.254: TP38.1 167.87,54.1 125.22,54.1 v1(124.59,54.74)
INTVCC1: length 20.5
  TOP w0.254: U1.B3 v1(67.94,52.2)
  TOP w0.508: v1(61.39,59.86) 61.93,59.86 R1.2
  L5-INT3 w0.254: v1(67.94,52.2) 67.36,52.78 67.36,56.48 66.86,56.98 63.53,56.98 v2(63.22,57.28) 63.22,57.32 64.05,58.14 64.05,59.6 63.79,59.86 v1(61.39,59.86)
  BOTTOM w0.254: v1(67.94,52.2) 67.31,51.56 65.75,51.56 C12.2
  BOTTOM w0.508: v2(63.22,57.28) 63.61,56.9 R4.2
INTVCC2: length 19.6
  TOP w0.254: R16.2 v1(32.64,60.33) ; U2.B3 v1(39.24,52.2)
  L5-INT3 w0.254: v1(32.64,60.33) 33.27,60.33 33.71,59.89 33.71,57.96 v1(34.09,57.58) 37.24,57.58 38.65,56.17 38.65,52.79 v1(39.24,52.2)
  BOTTOM w0.254: C36.2 37.05,51.56 38.61,51.56 v1(39.24,52.2) ; v1(34.09,57.58) 34.53,57.58 35.21,56.9 R20.2
INTVCC3: length 50.5
  TOP w0.254: U3.B3 v1(97.16,52.2)
  TOP w0.508: R30.2 v2(90.86,60.33)
  L4-INT2 w0.254: v2(119.2,59.97) 118.72,60.45 90.98,60.45 v2(90.86,60.33) 90.86,59.82 93.4,57.28 96.27,57.28 96.56,56.98 96.56,52.79 v1(97.16,52.2)
  BOTTOM w0.254: C59.2 94.96,51.56 96.52,51.56 v1(97.16,52.2) ; R34.2 91.44,59.74 v2(90.86,60.33)
  BOTTOM w0.508: R48.2 v2(119.2,59.97)
INTVCC4: length 17.3
  TOP w0.254: U4.B3 v1(125.86,52.2)
  TOP w0.508: R44.2 v2(120.31,61.12)
  L4-INT2 w0.254: v1(125.86,52.2) 125.18,52.87 122.77,52.87 121.86,53.78 121.86,59.57 v2(120.31,61.12)
  BOTTOM w0.254: v1(125.86,52.2) 125.22,51.56 123.66,51.56 C82.2
ISN1: length 3.7
  TOP w0.254: U1.A3 v1(66.68,52.2)
  BOTTOM w0.254: v1(66.68,52.2) 66.23,52.64 C13.1 64.29,52.64 R15.2
ISN2: length 3.7
  TOP w0.254: U2.A3 v1(37.97,52.2)
  BOTTOM w0.254: R29.2 35.59,52.64 C37.1 37.53,52.64 v1(37.97,52.2)
ISN3: length 3.7
  TOP w0.254: U3.A3 v1(95.88,52.2)
  BOTTOM w0.254: R43.2 94.8,52.83 C60.1 95.44,52.2 v1(95.88,52.2)
ISN4: length 3.7
  TOP w0.254: U4.A3 v1(124.59,52.2)
  BOTTOM w0.254: R57.2 122.2,52.64 C83.1 124.14,52.2 v1(124.59,52.2)
ISP1: length 4
  TOP w0.254: U1.A4 v1(66.68,53.47)
  BOTTOM w0.254: v1(66.68,53.47) 66.1,54.04 C13.2 64.67,54.04 R13.2
ISP2: length 4.1
  TOP w0.254: U2.A4 v1(37.97,53.47)
  BOTTOM w0.254: v1(37.97,53.47) 37.66,53.47 C37.2 37.07,54.03 35.76,54.03 35.39,54.4 R27.2
ISP3: length 4
  TOP w0.254: U3.A4 v1(95.88,53.47)
  BOTTOM w0.254: R41.2 93.88,54.04 C60.2 95.57,53.47 v1(95.88,53.47)
ISP4: length 4.4
  TOP w0.254: U4.A4 v1(124.59,53.47)
  BOTTOM w0.254: R55.2 122.01,54.17 122.38,53.8 123.46,53.8 C83.2 124.27,53.47 v1(124.59,53.47)
MODE: length 134.7
  TOP w0.254: U1.A10 v1(66.68,62.36) ; U2.A10 v1(37.97,62.36) ; U3.A10 v1(95.88,62.36) ; U4.A10 v1(124.59,62.36)
  L4-INT2 w0.254: P2.2 25.55,61.55 33.18,61.55 33.98,62.36 v1(37.97,62.36)
  L5-INT3 w0.254: v1(124.59,62.36) 123.59,62.36 122.13,63.81 117.21,63.81 115.12,61.73 96.52,61.73 v1(95.88,62.36) 95.7,62.17 86.48,62.17 86.04,61.73 67.3,61.73 v1(66.68,62.36) 64.83,62.36 64.52,62.05 55.51,62.05 55.2,61.74 38.59,61.74 v1(37.97,62.36)
